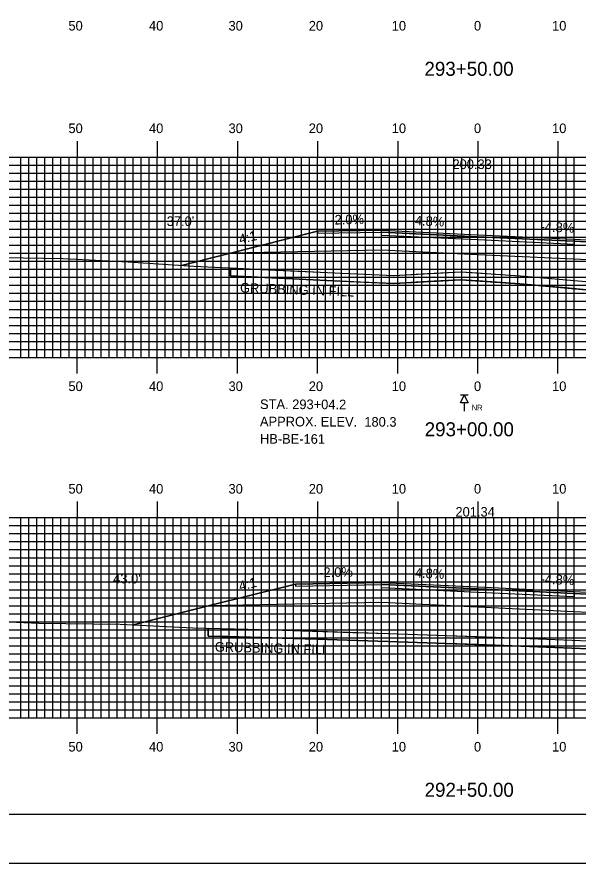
# Model space of a CAD drawing. Extents: x 1814128 to 1814471, y 442591 to 442811.
# Drawn here: x 1814236.5 to 1814306.5, y 442590.5 to 442696.2 of the extents above; entities that cross this region are included whole.
import ezdxf

# ---------------------------------------------------------------- set-up
doc = ezdxf.new("R2010")
doc.units = 0
for name, color, linetype in [('ANNOTATION', 7, 'Continuous'), ('BORDER', 7, 'Continuous'), ('BORING - NO REFUSAL', 7, 'Continuous'), ('D_Roadway_Centerline', 7, 'Continuous'), ('D_Roadway_Centerline_Text', 7, 'Continuous'), ('D_Roadway_Edge_Shoulder', 7, 'Continuous'), ('D_Roadway_Edge_TW', 7, 'Continuous'), ('D_Roadway_Pavement', 7, 'Continuous'), ('D_Roadway_SlopeLines', 7, 'Continuous'), ('D_Roadway_SubGrade', 7, 'Continuous'), ('D_Text_Standard', 7, 'Continuous'), ('GRUBBING IN FILL', 7, 'Continuous'), ('H_V ANNOTATION', 7, 'Continuous'), ('MAJOR', 7, 'Continuous'), ('MINOR', 7, 'Continuous'), ('PLOT BOUNDARY', 7, 'Continuous'), ('S_Roadway_Centerline', 7, 'Continuous')]:
    doc.layers.add(name, color=color, linetype=linetype)

msp = doc.modelspace()

# ---------------------------------------------------------------- linework, layer by layer
at = {"layer": 'BORDER'}
msp.add_lwpolyline([(1814144.39, 442596.67), (1814464.39, 442596.67), (1814464.39, 442806.67), (1814144.39, 442806.67)], close=True, dxfattribs=at)
at = {"layer": 'BORING - NO REFUSAL'}
for p, q in [((1814292.77, 442648.97), (1814291.81, 442648.97)), ((1814292.29, 442648.01), (1814292.29, 442646.95))]:
    msp.add_line(p, q, dxfattribs=at)
msp.add_lwpolyline([(1814292.29, 442648.97), (1814292.77, 442648.01), (1814291.81, 442648.01)], close=True, dxfattribs=at)
at = {"layer": 'D_Roadway_Centerline'}
for points in [[(1814257.01, 442665.16), (1814261.99, 442666.41), (1814263.12, 442666.69), (1814273.99, 442669.41), (1814281.99, 442669.57), (1814293.99, 442668.99), (1814305.99, 442668.42), (1814313.99, 442668.03), (1814326.37, 442664.94), (1814336.78, 442662.34)], [(1814250.99, 442620.3), (1814259.24, 442622.37), (1814260.37, 442622.65), (1814271.24, 442625.37), (1814281.99, 442625.58), (1814293.99, 442625.01), (1814305.99, 442624.43), (1814313.99, 442624.05), (1814326.37, 442620.95), (1814344.4, 442616.45)]]:
    msp.add_lwpolyline(points, dxfattribs=at)
at = {"layer": 'D_Roadway_Edge_Shoulder'}
for points in [[(1814281.99, 442669.57), (1814273.99, 442669.41), (1814273.99, 442669.16), (1814281.99, 442669.32)], [(1814305.99, 442668.42), (1814313.99, 442668.03), (1814313.99, 442667.78), (1814305.99, 442668.17)], [(1814281.99, 442625.58), (1814271.24, 442625.37), (1814271.24, 442625.12), (1814281.99, 442625.33)], [(1814305.99, 442624.43), (1814313.99, 442624.05), (1814313.99, 442623.8), (1814305.99, 442624.18)]]:
    msp.add_lwpolyline(points, close=True, dxfattribs=at)
at = {"layer": 'D_Roadway_Edge_TW'}
for points in [[(1814281.99, 442669.32), (1814281.99, 442669.57), (1814293.99, 442668.99), (1814305.99, 442668.42), (1814305.99, 442668.17), (1814293.99, 442668.74)], [(1814281.99, 442625.33), (1814281.99, 442625.58), (1814293.99, 442625.01), (1814305.99, 442624.43), (1814305.99, 442624.18), (1814293.99, 442624.76)]]:
    msp.add_lwpolyline(points, close=True, dxfattribs=at)
at = {"layer": 'D_Roadway_Pavement'}
for points in [[(1814281.99, 442668.9), (1814281.99, 442669.32), (1814293.99, 442668.74), (1814305.99, 442668.17), (1814305.99, 442667.75), (1814293.99, 442668.33)], [(1814281.99, 442624.92), (1814281.99, 442625.33), (1814293.99, 442624.76), (1814305.99, 442624.18), (1814305.99, 442623.77), (1814293.99, 442624.34)]]:
    msp.add_lwpolyline(points, close=True, dxfattribs=at)
at = {"layer": 'D_Roadway_SlopeLines'}
for points in [[(1814273.99, 442669.41), (1814263.12, 442666.69), (1814261.99, 442666.41), (1814257.01, 442665.16)], [(1814271.24, 442625.37), (1814260.37, 442622.65), (1814259.24, 442622.37), (1814250.99, 442620.3)]]:
    msp.add_lwpolyline(points, dxfattribs=at)
at = {"layer": 'D_Roadway_SubGrade'}
for points in [[(1814281.99, 442667.07), (1814263.12, 442666.69), (1814273.99, 442669.41), (1814273.99, 442669.16), (1814281.99, 442669.32), (1814293.99, 442668.74), (1814305.99, 442668.17), (1814313.99, 442667.78), (1814313.99, 442668.03), (1814326.37, 442664.94), (1814305.99, 442665.92), (1814293.99, 442666.49)], [(1814281.99, 442623.08), (1814260.37, 442622.65), (1814271.24, 442625.37), (1814271.24, 442625.12), (1814281.99, 442625.33), (1814293.99, 442624.76), (1814305.99, 442624.18), (1814313.99, 442623.8), (1814313.99, 442624.05), (1814326.37, 442620.95), (1814305.99, 442621.93), (1814293.99, 442622.51)]]:
    msp.add_lwpolyline(points, close=True, dxfattribs=at)
at = {"layer": 'GRUBBING IN FILL'}
for p, q in [((1814263.12, 442664.84), (1814263.12, 442663.84)), ((1814263.12, 442664.84), (1814263.12, 442663.84)), ((1814260.37, 442619.87), (1814260.37, 442618.87)), ((1814260.37, 442619.87), (1814260.37, 442618.87))]:
    msp.add_line(p, q, dxfattribs=at)
for points in [[(1814263.12, 442664.84), (1814266.9, 442664.66), (1814275.22, 442664.27), (1814283.53, 442663.9), (1814287.7, 442664.13), (1814291.88, 442664.37), (1814293.99, 442664.22), (1814293.99, 442663.22), (1814291.88, 442663.36), (1814287.7, 442663.13), (1814283.53, 442662.9), (1814279.35, 442663.08), (1814275.17, 442663.27), (1814269.15, 442663.56), (1814263.12, 442663.84)], [(1814263.12, 442664.84), (1814266.9, 442664.66), (1814275.22, 442664.27), (1814283.53, 442663.9), (1814287.7, 442664.13), (1814291.88, 442664.37), (1814293.99, 442664.22), (1814293.99, 442663.22), (1814291.88, 442663.36), (1814287.7, 442663.13), (1814283.53, 442662.9), (1814279.35, 442663.08), (1814275.17, 442663.27), (1814269.15, 442663.56), (1814263.12, 442663.84)], [(1814293.99, 442664.22), (1814295.6, 442664.12), (1814299.32, 442663.86), (1814304.12, 442663.43), (1814308.93, 442663), (1814312.83, 442662.93), (1814316.73, 442662.86), (1814321.15, 442662.61), (1814325.57, 442662.36), (1814326.37, 442662.35), (1814326.37, 442661.35), (1814325.53, 442661.36), (1814321.11, 442661.61), (1814316.69, 442661.86), (1814312.78, 442661.93), (1814308.87, 442662), (1814304.05, 442662.43), (1814299.24, 442662.87), (1814293.99, 442663.22)], [(1814293.99, 442664.22), (1814295.6, 442664.12), (1814299.32, 442663.86), (1814304.12, 442663.43), (1814308.93, 442663), (1814312.83, 442662.93), (1814316.73, 442662.86), (1814321.15, 442662.61), (1814325.57, 442662.36), (1814326.37, 442662.35), (1814326.37, 442661.35), (1814325.53, 442661.36), (1814321.11, 442661.61), (1814316.69, 442661.86), (1814312.78, 442661.93), (1814308.87, 442662), (1814304.05, 442662.43), (1814299.24, 442662.87), (1814293.99, 442663.22)], [(1814260.37, 442619.87), (1814261.86, 442619.83), (1814269.62, 442619.62), (1814278.39, 442619.35), (1814282.83, 442619.21), (1814290.06, 442618.96), (1814293.99, 442618.82), (1814293.99, 442617.82), (1814290.02, 442617.96), (1814282.8, 442618.22), (1814273.92, 442618.48), (1814262.82, 442618.81), (1814260.37, 442618.87)], [(1814260.37, 442619.87), (1814261.86, 442619.83), (1814269.62, 442619.62), (1814278.39, 442619.35), (1814282.83, 442619.21), (1814290.06, 442618.96), (1814293.99, 442618.82), (1814293.99, 442617.82), (1814290.02, 442617.96), (1814282.8, 442618.22), (1814273.92, 442618.48), (1814262.82, 442618.81), (1814260.37, 442618.87)], [(1814293.99, 442618.82), (1814297.29, 442618.7), (1814305.76, 442618.38), (1814314.23, 442618.05), (1814320.92, 442617.59), (1814325.63, 442617.32), (1814326.37, 442617.28), (1814326.37, 442616.28), (1814323.61, 442616.44), (1814320.86, 442616.6), (1814314.18, 442617.05), (1814305.72, 442617.38), (1814297.25, 442617.7), (1814293.99, 442617.82)], [(1814293.99, 442618.82), (1814297.29, 442618.7), (1814305.76, 442618.38), (1814314.23, 442618.05), (1814320.92, 442617.59), (1814325.63, 442617.32), (1814326.37, 442617.28), (1814326.37, 442616.28), (1814323.61, 442616.44), (1814320.86, 442616.6), (1814314.18, 442617.05), (1814305.72, 442617.38), (1814297.25, 442617.7), (1814293.99, 442617.82)]]:
    msp.add_lwpolyline(points, close=True, dxfattribs=at)
for points in [[(1814263.12, 442663.84), (1814275.17, 442663.27), (1814283.53, 442662.9), (1814291.88, 442663.36), (1814299.24, 442662.87), (1814308.87, 442662), (1814316.69, 442661.86), (1814325.53, 442661.36), (1814326.37, 442661.35)], [(1814263.12, 442663.84), (1814275.17, 442663.27), (1814283.53, 442662.9), (1814291.88, 442663.36), (1814299.24, 442662.87), (1814308.87, 442662), (1814316.69, 442661.86), (1814325.53, 442661.36), (1814326.37, 442661.35)], [(1814260.37, 442618.87), (1814265.26, 442618.76), (1814273.92, 442618.48), (1814282.8, 442618.22), (1814297.25, 442617.7), (1814314.18, 442617.05), (1814320.86, 442616.6), (1814326.37, 442616.28)], [(1814260.37, 442618.87), (1814265.26, 442618.76), (1814273.92, 442618.48), (1814282.8, 442618.22), (1814297.25, 442617.7), (1814314.18, 442617.05), (1814320.86, 442616.6), (1814326.37, 442616.28)]]:
    msp.add_lwpolyline(points, dxfattribs=at)
at = {"layer": 'MAJOR'}
for p, q in [((1814243.99, 442680.67), (1814243.99, 442678.67)), ((1814253.99, 442680.67), (1814253.99, 442678.67)), ((1814263.99, 442680.67), (1814263.99, 442678.67)), ((1814273.99, 442680.67), (1814273.99, 442678.67)), ((1814283.99, 442680.67), (1814283.99, 442678.67)), ((1814293.99, 442680.67), (1814293.99, 442678.67)), ((1814303.99, 442680.67), (1814303.99, 442678.67)), ((1814153.99, 442678.67), (1814433.99, 442678.67)), ((1814153.99, 442678.67), (1814433.99, 442678.67)), ((1814243.99, 442653.67), (1814243.99, 442678.67)), ((1814253.99, 442653.67), (1814253.99, 442678.67)), ((1814263.99, 442653.67), (1814263.99, 442678.67)), ((1814273.99, 442653.67), (1814273.99, 442678.67)), ((1814283.99, 442653.67), (1814283.99, 442678.67)), ((1814293.99, 442653.67), (1814293.99, 442678.67)), ((1814303.99, 442653.67), (1814303.99, 442678.67)), ((1814153.99, 442673.67), (1814433.99, 442673.67)), ((1814153.99, 442668.67), (1814433.99, 442668.67)), ((1814153.99, 442663.67), (1814433.99, 442663.67)), ((1814153.99, 442658.67), (1814433.99, 442658.67)), ((1814153.99, 442653.67), (1814433.99, 442653.67)), ((1814153.99, 442653.67), (1814433.99, 442653.67)), ((1814243.99, 442651.66), (1814243.99, 442653.67)), ((1814253.99, 442651.66), (1814253.99, 442653.67)), ((1814263.99, 442651.66), (1814263.99, 442653.67)), ((1814273.99, 442651.66), (1814273.99, 442653.67)), ((1814283.99, 442651.66), (1814283.99, 442653.67)), ((1814293.99, 442651.66), (1814293.99, 442653.67)), ((1814303.99, 442651.66), (1814303.99, 442653.67)), ((1814243.99, 442635.67), (1814243.99, 442633.67)), ((1814253.99, 442635.67), (1814253.99, 442633.67)), ((1814263.99, 442635.67), (1814263.99, 442633.67)), ((1814273.99, 442635.67), (1814273.99, 442633.67)), ((1814283.99, 442635.67), (1814283.99, 442633.67)), ((1814293.99, 442635.67), (1814293.99, 442633.67)), ((1814303.99, 442635.67), (1814303.99, 442633.67)), ((1814153.99, 442633.67), (1814433.99, 442633.67)), ((1814153.99, 442633.67), (1814433.99, 442633.67)), ((1814243.99, 442608.67), (1814243.99, 442633.67)), ((1814253.99, 442608.67), (1814253.99, 442633.67)), ((1814263.99, 442608.67), (1814263.99, 442633.67)), ((1814273.99, 442608.67), (1814273.99, 442633.67)), ((1814283.99, 442608.67), (1814283.99, 442633.67)), ((1814293.99, 442608.67), (1814293.99, 442633.67)), ((1814303.99, 442608.67), (1814303.99, 442633.67)), ((1814153.99, 442628.67), (1814433.99, 442628.67)), ((1814153.99, 442623.67), (1814433.99, 442623.67)), ((1814153.99, 442618.67), (1814433.99, 442618.67)), ((1814153.99, 442613.67), (1814433.99, 442613.67)), ((1814153.99, 442608.67), (1814433.99, 442608.67)), ((1814153.99, 442608.67), (1814433.99, 442608.67)), ((1814243.99, 442606.66), (1814243.99, 442608.67)), ((1814253.99, 442606.66), (1814253.99, 442608.67)), ((1814263.99, 442606.66), (1814263.99, 442608.67)), ((1814273.99, 442606.66), (1814273.99, 442608.67)), ((1814283.99, 442606.66), (1814283.99, 442608.67)), ((1814293.99, 442606.66), (1814293.99, 442608.67)), ((1814303.99, 442606.66), (1814303.99, 442608.67))]:
    msp.add_line(p, q, dxfattribs=at)
at = {"layer": 'MINOR'}
for p, q in [((1814236.99, 442653.67), (1814236.99, 442678.67)), ((1814237.99, 442653.67), (1814237.99, 442678.67)), ((1814238.99, 442653.67), (1814238.99, 442678.67)), ((1814239.99, 442653.67), (1814239.99, 442678.67)), ((1814240.99, 442653.67), (1814240.99, 442678.67)), ((1814241.99, 442653.67), (1814241.99, 442678.67)), ((1814242.99, 442653.67), (1814242.99, 442678.67)), ((1814244.99, 442653.67), (1814244.99, 442678.67)), ((1814245.99, 442653.67), (1814245.99, 442678.67)), ((1814246.99, 442653.67), (1814246.99, 442678.67)), ((1814247.99, 442653.67), (1814247.99, 442678.67)), ((1814248.99, 442653.67), (1814248.99, 442678.67)), ((1814249.99, 442653.67), (1814249.99, 442678.67)), ((1814250.99, 442653.67), (1814250.99, 442678.67)), ((1814251.99, 442653.67), (1814251.99, 442678.67)), ((1814252.99, 442653.67), (1814252.99, 442678.67)), ((1814254.99, 442653.67), (1814254.99, 442678.67)), ((1814255.99, 442653.67), (1814255.99, 442678.67)), ((1814256.99, 442653.67), (1814256.99, 442678.67)), ((1814257.99, 442653.67), (1814257.99, 442678.67)), ((1814258.99, 442653.67), (1814258.99, 442678.67)), ((1814259.99, 442653.67), (1814259.99, 442678.67)), ((1814260.99, 442653.67), (1814260.99, 442678.67)), ((1814261.99, 442653.67), (1814261.99, 442678.67)), ((1814262.99, 442653.67), (1814262.99, 442678.67)), ((1814264.99, 442653.67), (1814264.99, 442678.67)), ((1814265.99, 442653.67), (1814265.99, 442678.67)), ((1814266.99, 442653.67), (1814266.99, 442678.67)), ((1814267.99, 442653.67), (1814267.99, 442678.67)), ((1814268.99, 442653.67), (1814268.99, 442678.67)), ((1814269.99, 442653.67), (1814269.99, 442678.67)), ((1814270.99, 442653.67), (1814270.99, 442678.67)), ((1814271.99, 442653.67), (1814271.99, 442678.67)), ((1814272.99, 442653.67), (1814272.99, 442678.67)), ((1814274.99, 442653.67), (1814274.99, 442678.67)), ((1814275.99, 442653.67), (1814275.99, 442678.67)), ((1814276.99, 442653.67), (1814276.99, 442678.67)), ((1814277.99, 442653.67), (1814277.99, 442678.67)), ((1814278.99, 442653.67), (1814278.99, 442678.67)), ((1814279.99, 442653.67), (1814279.99, 442678.67)), ((1814280.99, 442653.67), (1814280.99, 442678.67)), ((1814281.99, 442653.67), (1814281.99, 442678.67)), ((1814282.99, 442653.67), (1814282.99, 442678.67)), ((1814284.99, 442653.67), (1814284.99, 442678.67)), ((1814285.99, 442653.67), (1814285.99, 442678.67)), ((1814286.99, 442653.67), (1814286.99, 442678.67)), ((1814287.99, 442653.67), (1814287.99, 442678.67)), ((1814288.99, 442653.67), (1814288.99, 442678.67)), ((1814289.99, 442653.67), (1814289.99, 442678.67)), ((1814290.99, 442653.67), (1814290.99, 442678.67)), ((1814291.99, 442653.67), (1814291.99, 442678.67)), ((1814292.99, 442653.67), (1814292.99, 442678.67)), ((1814294.99, 442653.67), (1814294.99, 442678.67)), ((1814295.99, 442653.67), (1814295.99, 442678.67)), ((1814296.99, 442653.67), (1814296.99, 442678.67)), ((1814297.99, 442653.67), (1814297.99, 442678.67)), ((1814298.99, 442653.67), (1814298.99, 442678.67)), ((1814299.99, 442653.67), (1814299.99, 442678.67)), ((1814300.99, 442653.67), (1814300.99, 442678.67)), ((1814301.99, 442653.67), (1814301.99, 442678.67)), ((1814302.99, 442653.67), (1814302.99, 442678.67)), ((1814304.99, 442653.67), (1814304.99, 442678.67)), ((1814305.99, 442653.67), (1814305.99, 442678.67)), ((1814153.99, 442677.67), (1814433.99, 442677.67)), ((1814153.99, 442676.67), (1814433.99, 442676.67)), ((1814153.99, 442675.67), (1814433.99, 442675.67)), ((1814153.99, 442674.67), (1814433.99, 442674.67)), ((1814153.99, 442672.67), (1814433.99, 442672.67)), ((1814153.99, 442671.67), (1814433.99, 442671.67)), ((1814153.99, 442670.67), (1814433.99, 442670.67)), ((1814153.99, 442669.67), (1814433.99, 442669.67)), ((1814153.99, 442667.67), (1814433.99, 442667.67)), ((1814153.99, 442666.67), (1814433.99, 442666.67)), ((1814153.99, 442665.67), (1814433.99, 442665.67)), ((1814153.99, 442664.67), (1814433.99, 442664.67)), ((1814153.99, 442662.67), (1814433.99, 442662.67)), ((1814153.99, 442661.67), (1814433.99, 442661.67)), ((1814153.99, 442660.67), (1814433.99, 442660.67)), ((1814153.99, 442659.67), (1814433.99, 442659.67)), ((1814153.99, 442657.67), (1814433.99, 442657.67)), ((1814153.99, 442656.67), (1814433.99, 442656.67)), ((1814153.99, 442655.67), (1814433.99, 442655.67)), ((1814153.99, 442654.67), (1814433.99, 442654.67)), ((1814236.99, 442608.67), (1814236.99, 442633.67)), ((1814237.99, 442608.67), (1814237.99, 442633.67)), ((1814238.99, 442608.67), (1814238.99, 442633.67)), ((1814239.99, 442608.67), (1814239.99, 442633.67)), ((1814240.99, 442608.67), (1814240.99, 442633.67)), ((1814241.99, 442608.67), (1814241.99, 442633.67)), ((1814242.99, 442608.67), (1814242.99, 442633.67)), ((1814244.99, 442608.67), (1814244.99, 442633.67)), ((1814245.99, 442608.67), (1814245.99, 442633.67)), ((1814246.99, 442608.67), (1814246.99, 442633.67)), ((1814247.99, 442608.67), (1814247.99, 442633.67)), ((1814248.99, 442608.67), (1814248.99, 442633.67)), ((1814249.99, 442608.67), (1814249.99, 442633.67)), ((1814250.99, 442608.67), (1814250.99, 442633.67)), ((1814251.99, 442608.67), (1814251.99, 442633.67)), ((1814252.99, 442608.67), (1814252.99, 442633.67)), ((1814254.99, 442608.67), (1814254.99, 442633.67)), ((1814255.99, 442608.67), (1814255.99, 442633.67)), ((1814256.99, 442608.67), (1814256.99, 442633.67)), ((1814257.99, 442608.67), (1814257.99, 442633.67)), ((1814258.99, 442608.67), (1814258.99, 442633.67)), ((1814259.99, 442608.67), (1814259.99, 442633.67)), ((1814260.99, 442608.67), (1814260.99, 442633.67)), ((1814261.99, 442608.67), (1814261.99, 442633.67)), ((1814262.99, 442608.67), (1814262.99, 442633.67)), ((1814264.99, 442608.67), (1814264.99, 442633.67)), ((1814265.99, 442608.67), (1814265.99, 442633.67)), ((1814266.99, 442608.67), (1814266.99, 442633.67)), ((1814267.99, 442608.67), (1814267.99, 442633.67)), ((1814268.99, 442608.67), (1814268.99, 442633.67)), ((1814269.99, 442608.67), (1814269.99, 442633.67)), ((1814270.99, 442608.67), (1814270.99, 442633.67)), ((1814271.99, 442608.67), (1814271.99, 442633.67)), ((1814272.99, 442608.67), (1814272.99, 442633.67)), ((1814274.99, 442608.67), (1814274.99, 442633.67)), ((1814275.99, 442608.67), (1814275.99, 442633.67)), ((1814276.99, 442608.67), (1814276.99, 442633.67)), ((1814277.99, 442608.67), (1814277.99, 442633.67)), ((1814278.99, 442608.67), (1814278.99, 442633.67)), ((1814279.99, 442608.67), (1814279.99, 442633.67)), ((1814280.99, 442608.67), (1814280.99, 442633.67)), ((1814281.99, 442608.67), (1814281.99, 442633.67)), ((1814282.99, 442608.67), (1814282.99, 442633.67)), ((1814284.99, 442608.67), (1814284.99, 442633.67)), ((1814285.99, 442608.67), (1814285.99, 442633.67)), ((1814286.99, 442608.67), (1814286.99, 442633.67)), ((1814287.99, 442608.67), (1814287.99, 442633.67)), ((1814288.99, 442608.67), (1814288.99, 442633.67)), ((1814289.99, 442608.67), (1814289.99, 442633.67)), ((1814290.99, 442608.67), (1814290.99, 442633.67)), ((1814291.99, 442608.67), (1814291.99, 442633.67)), ((1814292.99, 442608.67), (1814292.99, 442633.67)), ((1814294.99, 442608.67), (1814294.99, 442633.67)), ((1814295.99, 442608.67), (1814295.99, 442633.67)), ((1814296.99, 442608.67), (1814296.99, 442633.67)), ((1814297.99, 442608.67), (1814297.99, 442633.67)), ((1814298.99, 442608.67), (1814298.99, 442633.67)), ((1814299.99, 442608.67), (1814299.99, 442633.67)), ((1814300.99, 442608.67), (1814300.99, 442633.67)), ((1814301.99, 442608.67), (1814301.99, 442633.67)), ((1814302.99, 442608.67), (1814302.99, 442633.67)), ((1814304.99, 442608.67), (1814304.99, 442633.67)), ((1814305.99, 442608.67), (1814305.99, 442633.67)), ((1814153.99, 442632.67), (1814433.99, 442632.67)), ((1814153.99, 442631.67), (1814433.99, 442631.67)), ((1814153.99, 442630.67), (1814433.99, 442630.67)), ((1814153.99, 442629.67), (1814433.99, 442629.67)), ((1814153.99, 442627.67), (1814433.99, 442627.67)), ((1814153.99, 442626.67), (1814433.99, 442626.67)), ((1814153.99, 442625.67), (1814433.99, 442625.67)), ((1814153.99, 442624.67), (1814433.99, 442624.67)), ((1814153.99, 442622.67), (1814433.99, 442622.67)), ((1814153.99, 442621.67), (1814433.99, 442621.67)), ((1814153.99, 442620.67), (1814433.99, 442620.67)), ((1814153.99, 442619.67), (1814433.99, 442619.67)), ((1814153.99, 442617.67), (1814433.99, 442617.67)), ((1814153.99, 442616.67), (1814433.99, 442616.67)), ((1814153.99, 442615.67), (1814433.99, 442615.67)), ((1814153.99, 442614.67), (1814433.99, 442614.67)), ((1814153.99, 442612.67), (1814433.99, 442612.67)), ((1814153.99, 442611.67), (1814433.99, 442611.67)), ((1814153.99, 442610.67), (1814433.99, 442610.67)), ((1814153.99, 442609.67), (1814433.99, 442609.67))]:
    msp.add_line(p, q, dxfattribs=at)
at = {"layer": 'PLOT BOUNDARY'}
msp.add_lwpolyline([(1814128.21, 442590.55), (1814468.21, 442590.55), (1814468.21, 442810.55), (1814128.21, 442810.55)], close=True, dxfattribs=at)
at = {"layer": 'S_Roadway_Centerline'}
for points in [[(1814153.99, 442667.97), (1814161.32, 442667.4), (1814167.95, 442667.05), (1814174.94, 442666.98), (1814184.48, 442667.03), (1814193.54, 442667.21), (1814201.48, 442666.94), (1814209.68, 442667.06), (1814217.54, 442666.63), (1814226.05, 442666.58), (1814234.88, 442666.16), (1814242.26, 442666.03), (1814250.37, 442665.6), (1814258.58, 442665.06), (1814275.22, 442664.27), (1814283.53, 442663.9), (1814291.88, 442664.37), (1814299.32, 442663.86), (1814308.93, 442663), (1814316.73, 442662.86), (1814325.57, 442662.36), (1814332.4, 442662.3), (1814342.63, 442662.38), (1814356.37, 442661.7)], [(1814153.99, 442623.21), (1814163.78, 442622.13), (1814167.6, 442621.98), (1814184.17, 442621.87), (1814189.15, 442621.88), (1814200.08, 442621.51), (1814209.56, 442620.94), (1814215.95, 442620.64), (1814226.91, 442620.8), (1814232.69, 442620.8), (1814239.23, 442620.49), (1814249.37, 442620.39), (1814258.43, 442619.91), (1814265.29, 442619.76), (1814273.95, 442619.48), (1814282.83, 442619.21), (1814297.29, 442618.7), (1814314.23, 442618.05), (1814320.92, 442617.59), (1814330.34, 442617.05), (1814337.24, 442616.72), (1814347.7, 442616.32)]]:
    msp.add_lwpolyline(points, dxfattribs=at)

# ---------------------------------------------------------------- texts
at = {"layer": 'ANNOTATION'}
for s, rotation, p in [('-2.0%', 1.1458, (1814275.6, 442670.24)), ('4.8%', 357.2519, (1814286.12, 442670.17)), ('-4.8%', 357.2519, (1814301.8, 442669.42)), ('4:1', 14.0362, (1814264.35, 442667.8)), ('-2.0%', 1.1458, (1814274.22, 442626.23)), ('4.8%', 357.2519, (1814286.12, 442626.19)), ('4:1', 14.0362, (1814264.34, 442624.51)), ('-4.8%', 357.2519, (1814301.8, 442625.44))]:
    msp.add_text(s, height=1.2, rotation=rotation, dxfattribs=at).set_placement(p)
at = {"layer": 'BORING - NO REFUSAL'}
for s, p in [('STA. 293+04.2', (1814266.82, 442647.23)), ('APPROX. ELEV.  180.3', (1814266.81, 442645.07)), ('HB-BE-161', (1814266.81, 442642.91))]:
    msp.add_text(s, height=1.2, rotation=359.8142, dxfattribs=at).set_placement(p)
msp.add_text('NR', height=0.7, dxfattribs=at).set_placement((1814293.23, 442647.05))
at = {"layer": 'D_Roadway_Centerline'}
for s, p in [('C', (1814293.99, 442668.99)), ('L', (1814293.99, 442668.99)), ('C', (1814293.99, 442625.01)), ('L', (1814293.99, 442625))]:
    msp.add_text(s, height=0.0146, dxfattribs=at).set_placement(p)
at = {"layer": 'D_Roadway_Centerline_Text'}
for s, p in [('200.33', (1814290.83, 442677.18)), ('201.34', (1814291.2, 442633.79))]:
    msp.add_text(s, height=1.2, dxfattribs=at).set_placement(p)
at = {"layer": 'D_Text_Standard'}
for s, p in [("37.0'", (1814255.18, 442670.07)), ("43.0'", (1814248.5, 442625.46))]:
    msp.add_text(s, height=1.2, dxfattribs=at).set_placement(p)
at = {"layer": 'GRUBBING IN FILL'}
for rotation, p in [(357.9035, (1814264.31, 442661.78)), (358.5642, (1814261.17, 442616.95))]:
    msp.add_text('GRUBBING IN FILL', height=1.2, rotation=rotation, dxfattribs=at).set_placement(p)
at = {"layer": 'H_V ANNOTATION'}
for s, height, p in [('50', 1.2, (1814242.92, 442694.47)), ('40', 1.2, (1814252.97, 442694.47)), ('30', 1.2, (1814262.89, 442694.47)), ('20', 1.2, (1814272.9, 442694.47)), ('10', 1.2, (1814283.25, 442694.47)), ('0', 1.2, (1814293.51, 442694.47)), ('10', 1.2, (1814303.25, 442694.47)), ('293+50.00', 1.75, (1814287.33, 442688.82)), ('50', 1.2, (1814242.92, 442681.67)), ('40', 1.2, (1814252.97, 442681.67)), ('30', 1.2, (1814262.89, 442681.67)), ('20', 1.2, (1814272.9, 442681.67)), ('10', 1.2, (1814283.25, 442681.67)), ('0', 1.2, (1814293.51, 442681.67)), ('10', 1.2, (1814303.25, 442681.67)), ('50', 1.2, (1814242.92, 442649.47)), ('40', 1.2, (1814252.97, 442649.47)), ('30', 1.2, (1814262.89, 442649.47)), ('20', 1.2, (1814272.9, 442649.47)), ('10', 1.2, (1814283.25, 442649.47)), ('0', 1.2, (1814293.51, 442649.47)), ('10', 1.2, (1814303.25, 442649.47)), ('293+00.00', 1.75, (1814287.36, 442643.82)), ('50', 1.2, (1814242.92, 442636.67)), ('40', 1.2, (1814252.97, 442636.67)), ('30', 1.2, (1814262.89, 442636.67)), ('20', 1.2, (1814272.9, 442636.67)), ('10', 1.2, (1814283.25, 442636.67)), ('0', 1.2, (1814293.51, 442636.67)), ('10', 1.2, (1814303.25, 442636.67)), ('50', 1.2, (1814242.92, 442604.47)), ('40', 1.2, (1814252.97, 442604.47)), ('30', 1.2, (1814262.89, 442604.47)), ('20', 1.2, (1814272.9, 442604.47)), ('10', 1.2, (1814283.25, 442604.47)), ('0', 1.2, (1814293.51, 442604.47)), ('10', 1.2, (1814303.25, 442604.47)), ('292+50.00', 1.75, (1814287.35, 442598.82))]:
    msp.add_text(s, height=height, dxfattribs=at).set_placement(p)

doc.saveas('drawing.dxf')
